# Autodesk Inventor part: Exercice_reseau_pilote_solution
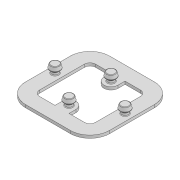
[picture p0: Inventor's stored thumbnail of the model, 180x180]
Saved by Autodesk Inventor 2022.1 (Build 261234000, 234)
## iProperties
Created: 2021-06
Part Number: Exercice_reseau_pilote_solution
Material: Générique
Document SubType Name: Modélisation
Designer: Fabian
Density: 1 g/cm^3
Appearance: Par défaut
Mass: 589.435 g
Surface Area: 1342.54 cm^2
Volume: 589.435 cm^3
Sheet Metal Rule: Par défaut
Author: Fabian
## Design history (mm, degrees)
sketch "Esquisse1"
  geometry: L1 (-80, 100)-(80, 100); L2 (100, 80)-(100, -80); L3 (80, -100)-(-80, -100); L4 (-100, -80)-(-100, 80); L5 (-100, 100)-(100, -100); L6 (100, 100)-(-100, -100); L7 (150, -80)-(150, 80); L8 (80, 150)-(-80, 150); L9 (-150, 80)-(-150, -80); L10 (-80, -150)-(80, -150); L11 (25, 100)-(25, 75); L12 (-25, 75)-(-25, 100); L13 (100, 0)-(-100, 0); L14 (25, -100)-(25, -75); L15 (-25, -75)-(-25, -100); A1 r 20 centre (80, 80) between (100, 80) and (80, 100); A2 r 20 centre (80, -80) between (80, -100) and (100, -80); A3 r 20 centre (-80, 80) between (-80, 100) and (-100, 80); A4 r 20 centre (-80, -80) between (-100, -80) and (-80, -100); A5 r 70 centre (80, 80) between (150, 80) and (80, 150); A6 r 70 centre (-80, 80) between (-80, 150) and (-150, 80); A7 r 70 centre (-80, -80) between (-150, -80) and (-80, -150); A8 r 70 centre (80, -80) between (80, -150) and (150, -80); A9 r 25 centre (0, 75) between (0, 50) and (25, 75); A10 r 25 centre (0, 75) between (-25, 75) and (0, 50); A11 r 25 centre (0, -75) between (25, -75) and (0, -50); A12 r 25 centre (0, -75) between (0, -50) and (-25, -75); 12 further points
  constraints: 30 end point, 24 point on circle, 14 point on line, 12 centre point, 11 symmetric about line, 10 tangent, 5 midpoint, 4 equal radius, 4 parallel, 4 perpendicular, 2 vertical, 1 horizontal, 1 vertical alignment, 17 other
  dimensions: "d1" = 200 distance of L6.start L5.end; "d4" = 50 distance between parallel lines of L2 L7 (= 0.25 x d1); "d6" = 50 distance of point (25, 50) point (-25, 50) (= d4); "d7" = 25 radius of A9; "d8" = 50 dimension on L1 (= d6); "d9" = 20 radius of A1
extrude "Extrusion1" new body sketch "Esquisse1" distance "d10" = 10; taper "d11" = 0 deg
sketch "Esquisse3"
  geometry: L1 (-150, 80)-(-150, -80) reference; L2 (-150, 0)-(-100, 0); L3 (-100, -80)-(-100, 80) reference; L4 (100, 80)-(100, -80) reference; L5 (100, 0)-(150, 0); L6 (150, -80)-(150, 80) reference; A1 r 25 centre (0, -75) between (25, -75) and (-25, -75) reference; A2 r 25 centre (0, 75) between (-25, 75) and (25, 75) reference; 5 further points
  constraints: 6 midpoint, 4 end point, 2 coincident, 1 horizontal alignment, 1 vertical alignment
sketch "Esquisse4"
  geometry: L1 (10, 75)-(40, 75); L2 (40, 75)-(40, 90); L3 (40, 90)-(26, 93.5); L4 (26, 93.5)-(20, 86.5); L5 (20, 86.5)-(10, 86.5); L6 (10, 86.5)-(10, 75); 1 further point
  constraints: 12 end point, 2 horizontal, 1 perpendicular, 1 vertical
  dimensions: "d12" = 30 distance of L1.start L1.end; "d13" = 23 diameter of L5 L1; "d15" = 30 horizontal distance of L2.end L1; "d16" = 37 diameter of L3.end L1; "d17" = 10 distance of L4.end L5.end; "d18" = 16 distance from line of L6 L3.end
revolve "Révolution1" sketch "Esquisse4" stored, may be unused: angle "d19" = 90 deg
fillet "Congé1" dims "d20" = 2
feature "Réseau basé sur une esquisse1"
node "Solide2"
other parameters: "Epaisseur" = 3.048 (derived), "FacteurX" = 4.4, "RayonPli" = 3.048 (= Epaisseur), "LargeurGrugeage" = 3.048 (= Epaisseur), "ProfondeurGrugeage" = 1.524 (= 0.5 x Epaisseur), "TailleGrugeage" = 12.192 (= 4 x Epaisseur), "JeuJointure" = 0.01, "RestesMinimum" = 6.096 (= 2 x Epaisseur), "Rayondetransition" = 3.048 (= RayonPli), "TailleRayonJacobi" = 3.048 (= RayonPli), "TailleJeu" = 3.048 (= Epaisseur)
